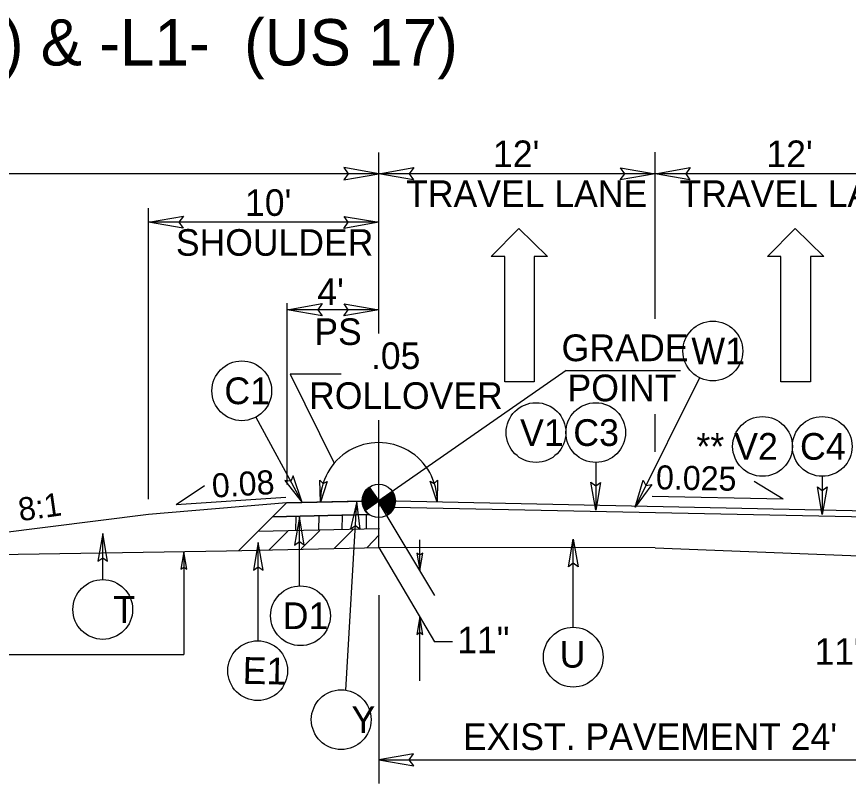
# Model space of a CAD drawing. Extents: x 2176024 to 2177225, y 75947 to 76635.
# Drawn here: x 2176790.13 to 2176826.22, y 76502.02 to 76535.28 of the extents above; entities that cross this region are included whole.
import ezdxf

# ---------------------------------------------------------------- set-up
doc = ezdxf.new("R2010")
doc.units = 0
for name, color, linetype in [('Exist XS Ground Line', 7, 'Continuous'), ('Old_Level_1', 7, 'Continuous'), ('Old_Level_11', 7, 'Continuous'), ('Old_Level_4', 7, 'Continuous'), ('Prop Dimension', 7, 'Continuous'), ('Typical Curb CELL', 7, 'Continuous'), ('Typical Grade Point Symbol CELL', 7, 'Continuous'), ('Typical Pavement Slope CELL', 7, 'Continuous'), ('Typical Pavement Slope Information CELL', 7, 'Continuous'), ('Typical Shoulder Slope CELL', 7, 'Continuous'), ('Typical Slope Point Local CELL', 7, 'Continuous'), ('Typical Terminator CELL', 7, 'Continuous'), ('Typical Text General CELL', 7, 'Continuous'), ('Typical Text Label CELL', 7, 'Continuous')]:
    doc.layers.add(name, color=color, linetype=linetype)

msp = doc.modelspace()

# ---------------------------------------------------------------- linework, layer by layer
at = {"layer": 'Exist XS Ground Line'}
for q in [(2176805.841, 76512.258), (2176829.841, 76511.758)]:
    msp.add_line((2176817.841, 76512.243), q, dxfattribs=at)
at = {"layer": 'Old_Level_1'}
for p, q in [((2176802.249, 76512.975), (2176802.258, 76513.606)), ((2176803.246, 76513), (2176803.255, 76513.628)), ((2176804.261, 76513.022), (2176804.27, 76513.651)), ((2176805.307, 76513.052), (2176805.316, 76513.674)), ((2176803.921, 76512.22), (2176804.748, 76513.047)), ((2176801.071, 76512.136), (2176801.898, 76512.963)), ((2176802.479, 76512.191), (2176803.284, 76512.996)), ((2176805.335, 76512.246), (2176805.861, 76512.8))]:
    msp.add_line(p, q, dxfattribs=at)
at = {"layer": 'Old_Level_11'}
for p, q in [((2176813.971, 76519.932), (2176805.841, 76514.272)), ((2176813.971, 76519.932), (2176818.943, 76519.932)), ((2176801.999, 76519.771), (2176803.911, 76515.915)), ((2176804.207, 76519.771), (2176801.999, 76519.771)), ((2176819.764, 76519.616), (2176816.969, 76514.003)), ((2176800.514, 76517.911), (2176802.521, 76514.203)), ((2176815.259, 76515.942), (2176815.259, 76513.877)), ((2176825.09, 76515.342), (2176825.09, 76513.678)), ((2176804.411, 76506.064), (2176804.895, 76514.253)), ((2176802.4, 76510.587), (2176802.4, 76513.565)), ((2176793.864, 76510.86), (2176793.864, 76512.86)), ((2176800.615, 76508.204), (2176800.615, 76512.473)), ((2176814.282, 76508.79), (2176814.282, 76512.619))]:
    msp.add_line(p, q, dxfattribs=at)
for points in [[(2176801.768, 76515.16), (2176802.521, 76514.203), (2176802.134, 76515.366), (2176802.02, 76515.13)], [(2176817.689, 76514.985), (2176816.969, 76514.003), (2176817.316, 76515.178), (2176817.439, 76514.946)], [(2176815.466, 76515.077), (2176815.259, 76513.877), (2176815.046, 76515.083), (2176815.259, 76514.93)], [(2176825.297, 76514.878), (2176825.09, 76513.678), (2176824.877, 76514.885), (2176825.09, 76514.731)], [(2176805.03, 76513.043), (2176804.895, 76514.253), (2176804.611, 76513.061), (2176804.833, 76513.201)], [(2176802.606, 76512.365), (2176802.4, 76513.565), (2176802.186, 76512.358), (2176802.4, 76512.511)], [(2176794.071, 76511.66), (2176793.864, 76512.86), (2176793.651, 76511.654), (2176793.864, 76511.807)], [(2176800.821, 76511.273), (2176800.615, 76512.473), (2176800.401, 76511.267), (2176800.614, 76511.42)], [(2176814.076, 76511.419), (2176814.282, 76512.619), (2176814.496, 76511.413), (2176814.282, 76511.566)]]:
    msp.add_lwpolyline(points, close=True, dxfattribs=at)
for centre in [(2176820.341, 76520.777), (2176799.897, 76519.051), (2176812.667, 76517.238), (2176815.259, 76517.238), (2176822.498, 76516.638), (2176825.09, 76516.638), (2176793.864, 76509.564), (2176802.445, 76509.292), (2176814.282, 76507.494), (2176800.588, 76506.908), (2176804.212, 76504.783)]:
    msp.add_circle(centre, 1.296, dxfattribs=at)
msp.add_arc((2176805.841, 76514.272), 2.534, 358.8065, 181.1935, dxfattribs=at)
at = {"layer": 'Old_Level_4'}
for p, q in [((2176810.727, 76524.876), (2176811.929, 76526.098)), ((2176811.929, 76526.098), (2176813.171, 76524.876)), ((2176822.717, 76524.876), (2176823.92, 76526.098)), ((2176823.92, 76526.098), (2176825.162, 76524.876)), ((2176811.309, 76524.876), (2176810.727, 76524.876)), ((2176811.309, 76519.444), (2176811.309, 76524.876)), ((2176813.171, 76524.876), (2176812.589, 76524.876)), ((2176812.589, 76524.876), (2176812.589, 76519.444)), ((2176823.299, 76524.876), (2176822.717, 76524.876)), ((2176823.299, 76519.444), (2176823.299, 76524.876)), ((2176825.162, 76524.876), (2176824.58, 76524.876)), ((2176824.58, 76524.876), (2176824.58, 76519.444)), ((2176812.589, 76519.444), (2176811.309, 76519.444)), ((2176824.58, 76519.444), (2176823.299, 76519.444))]:
    msp.add_line(p, q, dxfattribs=at)
at = {"layer": 'Prop Dimension'}
for p, q in [((2176805.841, 76521.541), (2176805.841, 76529.396)), ((2176817.841, 76522.172), (2176817.841, 76529.405)), ((2176805.841, 76528.468), (2176745.841, 76528.468)), ((2176817.841, 76528.468), (2176805.841, 76528.468)), ((2176829.841, 76528.468), (2176817.841, 76528.468)), ((2176795.844, 76514.344), (2176795.844, 76526.968)), ((2176805.844, 76526.36), (2176795.844, 76526.36)), ((2176801.874, 76514.979), (2176801.874, 76522.853)), ((2176805.844, 76522.57), (2176801.874, 76522.57)), ((2176805.841, 76514.272), (2176805.841, 76517.78)), ((2176817.841, 76516.404), (2176817.841, 76518.039)), ((2176805.796, 76514.259), (2176808.266, 76510.177)), ((2176807.629, 76511.252), (2176807.629, 76512.58)), ((2176797.385, 76512.068), (2176797.385, 76507.615)), ((2176805.841, 76512.258), (2176808.266, 76508.163)), ((2176805.841, 76510.183), (2176805.841, 76502.02)), ((2176807.629, 76506.463), (2176807.629, 76509.239)), ((2176809.046, 76508.163), (2176808.266, 76508.163)), ((2176784.475, 76507.615), (2176797.385, 76507.615)), ((2176805.841, 76503.045), (2176829.841, 76503.045))]:
    msp.add_line(p, q, dxfattribs=at)
at = {"layer": 'Typical Curb CELL'}
msp.add_line((2176805.841, 76512.258), (2176805.841, 76514.272), dxfattribs=at)
at = {"layer": 'Typical Grade Point Symbol CELL'}
for p, q in [((2176805.429, 76514.864), (2176805.841, 76514.272)), ((2176805.841, 76514.272), (2176806.432, 76514.684)), ((2176805.248, 76513.862), (2176805.841, 76514.272)), ((2176805.841, 76514.272), (2176805.248, 76513.862)), ((2176806.253, 76513.681), (2176805.841, 76514.272))]:
    msp.add_line(p, q, dxfattribs=at)
for points in [[(2176805.464, 76514.814), (2176805.225, 76514.648)], [(2176805.456, 76514.826), (2176805.244, 76514.679)], [(2176805.447, 76514.838), (2176805.271, 76514.715)], [(2176805.439, 76514.85), (2176805.305, 76514.756)], [(2176805.431, 76514.861), (2176805.366, 76514.817)], [(2176805.596, 76514.625), (2176805.12, 76514.294)], [(2176805.604, 76514.613), (2176805.12, 76514.276)], [(2176805.612, 76514.601), (2176805.12, 76514.259)], [(2176805.587, 76514.637), (2176805.121, 76514.312)], [(2176805.62, 76514.589), (2176805.121, 76514.242)], [(2176805.629, 76514.577), (2176805.121, 76514.224)], [(2176805.579, 76514.648), (2176805.122, 76514.33)], [(2176805.637, 76514.566), (2176805.123, 76514.208)], [(2176805.571, 76514.66), (2176805.124, 76514.349)], [(2176805.645, 76514.554), (2176805.124, 76514.191)], [(2176805.563, 76514.672), (2176805.126, 76514.368)], [(2176805.653, 76514.542), (2176805.126, 76514.175)], [(2176805.554, 76514.684), (2176805.128, 76514.387)], [(2176805.661, 76514.53), (2176805.129, 76514.16)], [(2176805.546, 76514.696), (2176805.132, 76514.408)], [(2176805.67, 76514.518), (2176805.132, 76514.144)], [(2176805.678, 76514.506), (2176805.135, 76514.129)], [(2176805.538, 76514.708), (2176805.137, 76514.429)], [(2176805.686, 76514.495), (2176805.138, 76514.113)], [(2176805.694, 76514.483), (2176805.141, 76514.098)], [(2176805.53, 76514.719), (2176805.142, 76514.45)], [(2176805.703, 76514.471), (2176805.145, 76514.083)], [(2176805.521, 76514.731), (2176805.148, 76514.471)], [(2176805.711, 76514.459), (2176805.149, 76514.068)], [(2176805.513, 76514.743), (2176805.154, 76514.493)], [(2176805.505, 76514.755), (2176805.162, 76514.516)], [(2176805.497, 76514.767), (2176805.171, 76514.54)], [(2176805.489, 76514.779), (2176805.181, 76514.564)], [(2176805.48, 76514.79), (2176805.194, 76514.591)], [(2176805.472, 76514.802), (2176805.208, 76514.618)], [(2176806.436, 76514.679), (2176806.436, 76514.679), (2176805.844, 76514.267)], [(2176806.444, 76514.667), (2176805.853, 76514.255)], [(2176806.451, 76514.654), (2176805.861, 76514.243)], [(2176806.46, 76514.642), (2176805.869, 76514.232)], [(2176806.466, 76514.63), (2176805.877, 76514.22)], [(2176806.473, 76514.617), (2176805.886, 76514.208)], [(2176806.48, 76514.604), (2176805.894, 76514.196)], [(2176806.487, 76514.591), (2176805.902, 76514.184)], [(2176806.494, 76514.579), (2176805.91, 76514.172)], [(2176806.5, 76514.565), (2176805.919, 76514.161)], [(2176806.505, 76514.551), (2176805.927, 76514.149)], [(2176806.511, 76514.538), (2176805.935, 76514.137)], [(2176806.517, 76514.524), (2176805.943, 76514.125)], [(2176806.521, 76514.51), (2176805.952, 76514.113)], [(2176806.526, 76514.496), (2176805.96, 76514.101)], [(2176806.531, 76514.481), (2176805.968, 76514.09)], [(2176806.535, 76514.467), (2176805.976, 76514.078)], [(2176806.539, 76514.452), (2176805.984, 76514.066)], [(2176805.719, 76514.447), (2176805.154, 76514.054)], [(2176805.727, 76514.435), (2176805.159, 76514.04)], [(2176805.736, 76514.424), (2176805.164, 76514.026)], [(2176805.744, 76514.412), (2176805.169, 76514.012)], [(2176805.752, 76514.4), (2176805.175, 76513.998)], [(2176805.76, 76514.388), (2176805.18, 76513.985)], [(2176805.769, 76514.376), (2176805.186, 76513.971)], [(2176805.777, 76514.364), (2176805.193, 76513.958)], [(2176805.785, 76514.353), (2176805.199, 76513.945)], [(2176805.793, 76514.341), (2176805.206, 76513.932)], [(2176805.801, 76514.329), (2176805.212, 76513.919)], [(2176805.81, 76514.317), (2176805.219, 76513.906)], [(2176805.818, 76514.305), (2176805.228, 76513.894)], [(2176805.826, 76514.293), (2176805.235, 76513.882)], [(2176805.834, 76514.282), (2176805.243, 76513.87), (2176805.243, 76513.87)], [(2176806.542, 76514.437), (2176805.993, 76514.054)], [(2176806.545, 76514.421), (2176806.001, 76514.042)], [(2176806.548, 76514.406), (2176806.009, 76514.03)], [(2176806.551, 76514.39), (2176806.017, 76514.019)], [(2176806.554, 76514.375), (2176806.026, 76514.007)], [(2176806.556, 76514.358), (2176806.034, 76513.995)], [(2176806.558, 76514.342), (2176806.042, 76513.983)], [(2176806.559, 76514.325), (2176806.05, 76513.971)], [(2176806.561, 76514.309), (2176806.059, 76513.959)], [(2176806.561, 76514.292), (2176806.067, 76513.948)], [(2176806.562, 76514.274), (2176806.075, 76513.936)], [(2176806.561, 76514.256), (2176806.083, 76513.924)], [(2176806.561, 76514.239), (2176806.092, 76513.912)], [(2176806.56, 76514.221), (2176806.1, 76513.9)], [(2176806.558, 76514.201), (2176806.108, 76513.888)], [(2176806.555, 76514.182), (2176806.116, 76513.877)], [(2176806.553, 76514.163), (2176806.124, 76513.865)], [(2176806.55, 76514.143), (2176806.133, 76513.853)], [(2176806.546, 76514.123), (2176806.141, 76513.841)], [(2176806.541, 76514.102), (2176806.149, 76513.829)], [(2176806.535, 76514.08), (2176806.157, 76513.817)], [(2176806.529, 76514.058), (2176806.166, 76513.806)], [(2176806.521, 76514.035), (2176806.174, 76513.794)], [(2176806.512, 76514.012), (2176806.182, 76513.782)], [(2176806.502, 76513.987), (2176806.19, 76513.77)], [(2176806.491, 76513.961), (2176806.199, 76513.758)], [(2176806.478, 76513.935), (2176806.207, 76513.746)], [(2176806.461, 76513.906), (2176806.215, 76513.735)], [(2176806.442, 76513.875), (2176806.223, 76513.723)], [(2176806.417, 76513.84), (2176806.232, 76513.711)], [(2176806.384, 76513.8), (2176806.24, 76513.699)], [(2176806.332, 76513.746), (2176806.248, 76513.687)]]:
    msp.add_lwpolyline(points, dxfattribs=at)
msp.add_circle((2176805.841, 76514.273), 0.721, dxfattribs=at)
for start, end in [(124.8249, 214.8249), (304.8249, 34.8249)]:
    msp.add_arc((2176805.841, 76514.273), 0.721, start, end, dxfattribs=at)
at = {"layer": 'Typical Pavement Slope CELL'}
for p, q in [((2176801.842, 76514.189), (2176799.763, 76512.122)), ((2176805.841, 76514.272), (2176805.841, 76514.022)), ((2176806.511, 76514.008), (2176829.841, 76513.522)), ((2176780.941, 76511.822), (2176799.228, 76512.11)), ((2176799.228, 76512.11), (2176805.891, 76512.259))]:
    msp.add_line(p, q, dxfattribs=at)
at = {"layer": 'Typical Pavement Slope Information CELL'}
for p, q in [((2176797.057, 76514.12), (2176798.281, 76514.939)), ((2176823.393, 76514.347), (2176822.132, 76515.109)), ((2176823.393, 76514.347), (2176817.708, 76514.461)), ((2176797.057, 76514.12), (2176801.803, 76514.433))]:
    msp.add_line(p, q, dxfattribs=at)
at = {"layer": 'Typical Shoulder Slope CELL'}
for p, q in [((2176801.842, 76514.189), (2176795.842, 76513.684)), ((2176795.842, 76513.684), (2176780.941, 76511.822)), ((2176805.435, 76513.677), (2176801.232, 76513.583)), ((2176805.871, 76513.065), (2176800.592, 76512.947))]:
    msp.add_line(p, q, dxfattribs=at)
at = {"layer": 'Typical Slope Point Local CELL'}
for p, q in [((2176801.842, 76514.189), (2176801.232, 76513.583)), ((2176801.842, 76514.189), (2176805.841, 76514.272)), ((2176805.12, 76514.257), (2176801.842, 76514.189)), ((2176805.121, 76514.224), (2176805.121, 76514.224)), ((2176805.126, 76514.175), (2176805.126, 76514.175)), ((2176805.141, 76514.098), (2176805.141, 76514.098)), ((2176806.541, 76514.102), (2176806.541, 76514.102)), ((2176806.546, 76514.123), (2176806.545, 76514.123)), ((2176806.55, 76514.143), (2176806.55, 76514.143)), ((2176806.553, 76514.163), (2176806.553, 76514.163)), ((2176806.56, 76514.221), (2176806.559, 76514.22)), ((2176829.841, 76513.772), (2176806.561, 76514.257)), ((2176806.561, 76514.239), (2176806.561, 76514.238)), ((2176805.145, 76514.083), (2176805.145, 76514.083)), ((2176805.154, 76514.054), (2176805.154, 76514.054)), ((2176805.186, 76513.971), (2176805.186, 76513.971)), ((2176805.199, 76513.945), (2176805.199, 76513.945)), ((2176805.206, 76513.932), (2176805.206, 76513.932)), ((2176805.212, 76513.919), (2176805.213, 76513.919)), ((2176805.219, 76513.906), (2176805.22, 76513.907)), ((2176805.235, 76513.882), (2176805.235, 76513.882)), ((2176805.243, 76513.87), (2176805.243, 76513.87)), ((2176805.248, 76513.862), (2176805.248, 76513.862)), ((2176806.511, 76514.008), (2176829.841, 76513.522)), ((2176806.521, 76514.035), (2176806.521, 76514.035)), ((2176806.529, 76514.058), (2176806.529, 76514.058)), ((2176801.232, 76513.583), (2176805.435, 76513.677))]:
    msp.add_line(p, q, dxfattribs=at)
for points in [[(2176805.121, 76514.224), (2176805.121, 76514.224)], [(2176805.126, 76514.175), (2176805.126, 76514.175)], [(2176805.141, 76514.098), (2176805.141, 76514.098)], [(2176806.541, 76514.102), (2176806.541, 76514.102)], [(2176806.546, 76514.123), (2176806.546, 76514.123)], [(2176806.55, 76514.143), (2176806.55, 76514.143)], [(2176806.553, 76514.163), (2176806.553, 76514.163)], [(2176806.559, 76514.221), (2176806.56, 76514.221)], [(2176806.561, 76514.239), (2176806.561, 76514.239)], [(2176805.145, 76514.083), (2176805.145, 76514.083)], [(2176805.154, 76514.054), (2176805.154, 76514.054)], [(2176805.186, 76513.971), (2176805.186, 76513.971)], [(2176805.199, 76513.945), (2176805.199, 76513.945)], [(2176805.206, 76513.932), (2176805.206, 76513.932)], [(2176805.213, 76513.919), (2176805.212, 76513.919)], [(2176805.22, 76513.907), (2176805.219, 76513.906)], [(2176805.235, 76513.882), (2176805.235, 76513.882)], [(2176805.243, 76513.87), (2176805.243, 76513.87)], [(2176805.249, 76513.862), (2176805.248, 76513.862)], [(2176806.521, 76514.035), (2176806.521, 76514.035)], [(2176806.529, 76514.058), (2176806.529, 76514.058)]]:
    msp.add_lwpolyline(points, dxfattribs=at)
for start, end in [(181.2548, 182.5146), (182.5146, 183.8761), (183.8895, 185.2021), (185.2021, 187.8094), (187.8245, 189.0767), (189.0767, 191.5882), (191.5882, 192.8361), (192.8361, 194.0754), (194.0907, 195.2968), (342.646, 346.2404), (346.2648, 347.9455), (347.9775, 349.598), (349.5984, 351.2038), (351.2196, 355.7778), (355.8127, 357.2394), (358.6425, 358.745), (357.2652, 358.6425), (195.2976, 196.5055), (196.5055, 197.7127), (197.7154, 201.2689), (201.2689, 204.7878), (204.7881, 205.9405), (205.9405, 207.109), (207.1121, 208.2646), (208.2653, 209.4175), (209.4186, 210.5682), (210.5718, 211.7158), (211.7158, 212.8649), (212.8666, 214.0118), (214.0122, 214.7719), (214.8249, 235.8001), (338.4481, 340.731), (340.7368, 342.6429)]:
    msp.add_arc((2176805.841, 76514.273), 0.721, start, end, dxfattribs=at)
at = {"layer": 'Typical Terminator CELL'}
for points in [[(2176804.331, 76528.208), (2176805.841, 76528.468), (2176804.323, 76528.736), (2176804.516, 76528.468)], [(2176807.35, 76528.208), (2176805.841, 76528.468), (2176807.359, 76528.736), (2176807.166, 76528.468)], [(2176816.331, 76528.728), (2176817.841, 76528.468), (2176816.323, 76528.2), (2176816.516, 76528.468)], [(2176819.35, 76528.208), (2176817.841, 76528.468), (2176819.359, 76528.736), (2176819.166, 76528.468)], [(2176797.354, 76526.1), (2176795.844, 76526.36), (2176797.362, 76526.628), (2176797.169, 76526.36)], [(2176804.334, 76526.62), (2176805.844, 76526.36), (2176804.326, 76526.091), (2176804.519, 76526.36)], [(2176803.384, 76522.31), (2176801.874, 76522.57), (2176803.392, 76522.839), (2176803.199, 76522.57)], [(2176804.334, 76522.83), (2176805.844, 76522.57), (2176804.326, 76522.302), (2176804.519, 76522.57)], [(2176803.609, 76515.122), (2176803.307, 76514.22), (2176803.286, 76515.177), (2176803.432, 76515.033)], [(2176808.397, 76515.171), (2176808.374, 76514.22), (2176808.072, 76515.128), (2176808.254, 76515.034)], [(2176797.515, 76511.314), (2176797.385, 76512.068), (2176797.251, 76511.309), (2176797.385, 76511.406)], [(2176807.497, 76512.007), (2176807.629, 76511.252), (2176807.761, 76512.012), (2176807.627, 76511.915)], [(2176807.761, 76508.484), (2176807.629, 76509.239), (2176807.497, 76508.479), (2176807.631, 76508.576)], [(2176807.35, 76503.305), (2176805.841, 76503.045), (2176807.359, 76502.776), (2176807.166, 76503.045)]]:
    msp.add_lwpolyline(points, close=True, dxfattribs=at)

# ---------------------------------------------------------------- texts
at = {"layer": 'Old_Level_11'}
for s, rotation, p in [('GRADE', 359.9998, (2176813.775, 76520.336)), ('W1', 359.9997, (2176819.41, 76520.197)), ('C1', 0.0003, (2176799.141, 76518.471)), ('POINT', 359.9998, (2176814.028, 76518.596)), ('V1', 0.0003, (2176811.974, 76516.658)), ('C3', 0.0003, (2176814.286, 76516.658)), ('** V2', 0.0003, (2176819.629, 76516.058)), ('C4', 0.0003, (2176824.124, 76516.058)), ('T', 0.0003, (2176794.321, 76508.984)), ('D1', 0.0003, (2176801.672, 76508.712)), ('U', 0.0003, (2176813.696, 76507.04)), ('E1', 358.8249, (2176799.927, 76506.341)), ('Y', 359.9997, (2176804.657, 76504.203))]:
    msp.add_text(s, height=1.16, rotation=rotation, dxfattribs=at).set_placement(p)
for p in [(2176809.25, 76507.663), (2176824.754, 76507.163)]:
    msp.add_text('11"', height=1.1533, dxfattribs=at).set_placement(p)
at = {"layer": 'Typical Pavement Slope Information CELL'}
for s, rotation, p in [('0.08', 3.5795, (2176798.633, 76514.411)), ('0.025', 358.8543, (2176817.866, 76514.779))]:
    msp.add_text(s, height=1.0429, rotation=rotation, dxfattribs=at).set_placement(p)
at = {"layer": 'Typical Slope Point Local CELL'}
msp.add_text('8:1', height=1.0064, rotation=8.0589, dxfattribs=at).set_placement((2176790.272, 76513.389))
at = {"layer": 'Typical Text General CELL'}
for s, height, p in [("12' ", 1.1533, (2176810.803, 76528.757)), ("12' ", 1.1533, (2176822.668, 76528.757)), ('TRAVEL LANE', 1.15334, (2176807.033, 76527.027)), ('TRAVEL LANE', 1.15334, (2176818.899, 76527.027)), ("10'", 1.1533, (2176800.039, 76526.64)), ('SHOULDER', 1.1533, (2176797.038, 76524.91)), ("4'", 1.1533, (2176803.176, 76522.77)), ('PS', 1.1533, (2176803.047, 76521.04)), ("EXIST. PAVEMENT 24'", 1.15334, (2176809.498, 76503.472))]:
    msp.add_text(s, height=height, dxfattribs=at).set_placement(p)
for s, p in [('.05', (2176805.505, 76519.997)), ('ROLLOVER', (2176802.82, 76518.267))]:
    msp.add_text(s, height=1.1533, rotation=360, dxfattribs=at).set_placement(p)
at = {"layer": 'Typical Text Label CELL'}
msp.add_text('C -L- (US 17) & -L1-  (US 17)', height=2.01314, dxfattribs=at).set_placement((2176774.42, 76533.164))

doc.saveas('drawing.dxf')
